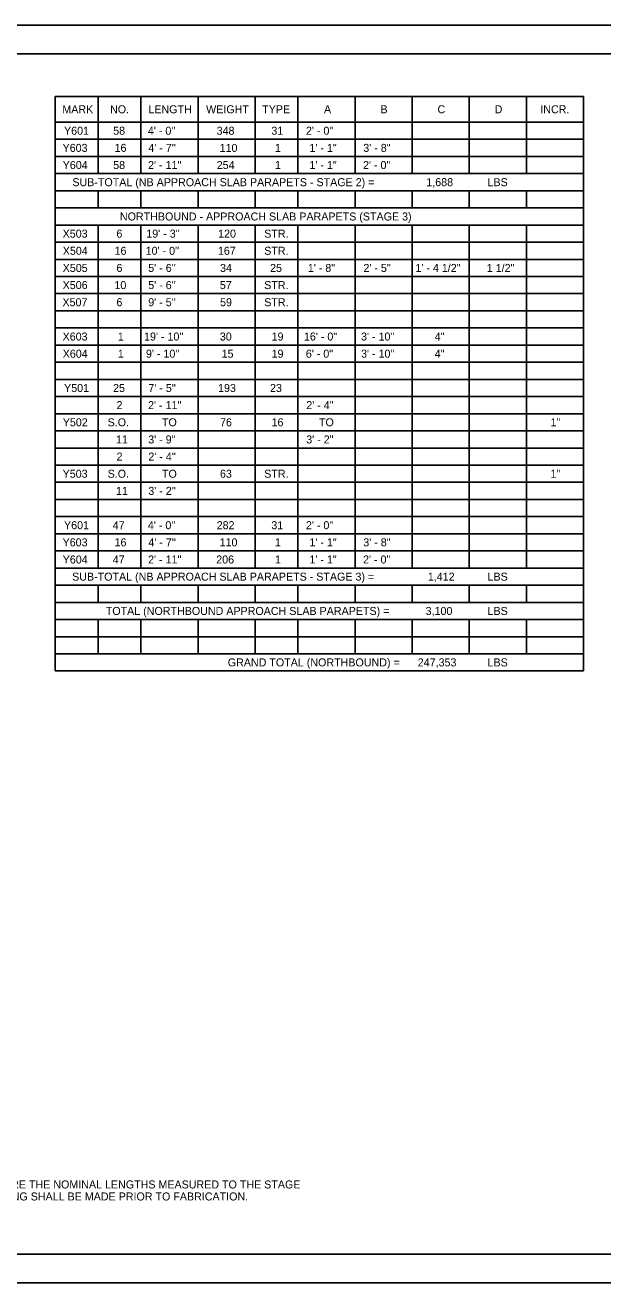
# Model space of a CAD drawing. Extents: x 1485751 to 1485785, y 230696.6 to 230718.6.
# Drawn here: x 1485763.13 to 1485773.25, y 230696.64 to 230718.64 of the extents above; entities that cross this region are included whole.
import ezdxf

# ---------------------------------------------------------------- set-up
doc = ezdxf.new("R2010")
doc.units = 0
for name, color, linetype in [('SH_Border', 7, 'Continuous'), ('SH_Cut_Line', 7, 'Continuous'), ('TX_P_Misc', 7, 'Continuous')]:
    doc.layers.add(name, color=color, linetype=linetype)

msp = doc.modelspace()

# ---------------------------------------------------------------- linework, layer by layer
at = {"layer": 'SH_Border'}
msp.add_lwpolyline([(1485753.033, 230718.141), (1485784.533, 230718.141), (1485784.533, 230697.141), (1485753.033, 230697.141)], close=True, dxfattribs=at)
at = {"layer": 'SH_Cut_Line'}
msp.add_lwpolyline([(1485751.033, 230718.641), (1485785.033, 230718.641), (1485785.033, 230696.641), (1485751.033, 230696.641)], close=True, dxfattribs=at)
at = {"layer": 'TX_P_Misc'}
for p, q in [((1485763.658, 230717.394), (1485772.908, 230717.394)), ((1485763.658, 230717.394), (1485763.658, 230707.344)), ((1485764.408, 230717.394), (1485764.408, 230716.044)), ((1485765.158, 230717.394), (1485765.158, 230716.044)), ((1485766.158, 230717.394), (1485766.158, 230716.044)), ((1485767.158, 230717.394), (1485767.158, 230716.044)), ((1485767.908, 230717.394), (1485767.908, 230716.044)), ((1485768.908, 230717.394), (1485768.908, 230716.044)), ((1485769.908, 230717.394), (1485769.908, 230716.044)), ((1485770.908, 230717.394), (1485770.908, 230716.044)), ((1485771.908, 230717.394), (1485771.908, 230716.044)), ((1485772.908, 230717.394), (1485772.908, 230707.344)), ((1485763.658, 230716.944), (1485772.908, 230716.944)), ((1485763.658, 230716.644), (1485772.908, 230716.644)), ((1485763.658, 230716.344), (1485772.908, 230716.344)), ((1485763.658, 230716.044), (1485772.908, 230716.044)), ((1485763.658, 230715.744), (1485772.908, 230715.744)), ((1485764.408, 230715.744), (1485764.408, 230715.444)), ((1485765.158, 230715.744), (1485765.158, 230715.444)), ((1485766.158, 230715.744), (1485766.158, 230715.444)), ((1485767.158, 230715.744), (1485767.158, 230715.444)), ((1485767.908, 230715.744), (1485767.908, 230715.444)), ((1485768.908, 230715.744), (1485768.908, 230715.444)), ((1485769.908, 230715.744), (1485769.908, 230715.444)), ((1485770.908, 230715.744), (1485770.908, 230715.444)), ((1485771.908, 230715.744), (1485771.908, 230715.444)), ((1485763.658, 230715.444), (1485772.908, 230715.444)), ((1485763.658, 230715.144), (1485772.908, 230715.144)), ((1485764.408, 230715.144), (1485764.408, 230709.144)), ((1485765.158, 230715.144), (1485765.158, 230709.144)), ((1485766.158, 230715.144), (1485766.158, 230709.144)), ((1485767.158, 230715.144), (1485767.158, 230709.144)), ((1485767.908, 230715.144), (1485767.908, 230709.144)), ((1485768.908, 230715.144), (1485768.908, 230709.144)), ((1485769.908, 230715.144), (1485769.908, 230709.144)), ((1485770.908, 230715.144), (1485770.908, 230709.144)), ((1485771.908, 230715.144), (1485771.908, 230709.144)), ((1485763.658, 230714.844), (1485772.908, 230714.844)), ((1485763.658, 230714.544), (1485772.908, 230714.544)), ((1485763.658, 230714.244), (1485772.908, 230714.244)), ((1485763.658, 230713.944), (1485772.908, 230713.944)), ((1485763.658, 230713.644), (1485772.908, 230713.644)), ((1485763.658, 230713.344), (1485772.908, 230713.344)), ((1485763.658, 230713.044), (1485772.908, 230713.044)), ((1485763.658, 230712.744), (1485772.908, 230712.744)), ((1485763.658, 230712.444), (1485772.908, 230712.444)), ((1485763.658, 230712.144), (1485772.908, 230712.144)), ((1485763.658, 230711.844), (1485772.908, 230711.844)), ((1485763.658, 230711.544), (1485772.908, 230711.544)), ((1485763.658, 230711.244), (1485772.908, 230711.244)), ((1485763.658, 230710.944), (1485772.908, 230710.944)), ((1485763.658, 230710.644), (1485772.908, 230710.644)), ((1485763.658, 230710.344), (1485772.908, 230710.344)), ((1485763.658, 230710.044), (1485772.908, 230710.044)), ((1485763.658, 230709.744), (1485772.908, 230709.744)), ((1485763.658, 230709.444), (1485772.908, 230709.444)), ((1485763.658, 230709.144), (1485772.908, 230709.144)), ((1485763.658, 230708.844), (1485772.908, 230708.844)), ((1485764.408, 230708.844), (1485764.408, 230708.544)), ((1485765.158, 230708.844), (1485765.158, 230708.544)), ((1485766.158, 230708.844), (1485766.158, 230708.544)), ((1485767.158, 230708.844), (1485767.158, 230708.544)), ((1485767.908, 230708.844), (1485767.908, 230708.544)), ((1485768.908, 230708.844), (1485768.908, 230708.544)), ((1485769.908, 230708.844), (1485769.908, 230708.544)), ((1485770.908, 230708.844), (1485770.908, 230708.544)), ((1485771.908, 230708.844), (1485771.908, 230708.544)), ((1485763.658, 230708.544), (1485772.908, 230708.544)), ((1485763.658, 230708.244), (1485772.908, 230708.244)), ((1485764.408, 230708.244), (1485764.408, 230707.644)), ((1485765.158, 230708.244), (1485765.158, 230707.644)), ((1485766.158, 230708.244), (1485766.158, 230707.644)), ((1485767.158, 230708.244), (1485767.158, 230707.644)), ((1485767.908, 230708.244), (1485767.908, 230707.644)), ((1485768.908, 230708.244), (1485768.908, 230707.644)), ((1485769.908, 230708.244), (1485769.908, 230707.644)), ((1485770.908, 230708.244), (1485770.908, 230707.644)), ((1485771.908, 230708.244), (1485771.908, 230707.644)), ((1485763.658, 230707.944), (1485772.908, 230707.944)), ((1485763.658, 230707.644), (1485772.908, 230707.644)), ((1485763.658, 230707.344), (1485772.908, 230707.344))]:
    msp.add_line(p, q, dxfattribs=at)

# ---------------------------------------------------------------- texts
for s, p in [('MARK', (1485763.782, 230717.099)), ('NO.', (1485764.618, 230717.099)), ('LENGTH', (1485765.288, 230717.099)), ('WEIGHT', (1485766.3, 230717.099)), ('TYPE', (1485767.282, 230717.099)), ('A', (1485768.364, 230717.099)), ('B', (1485769.353, 230717.099)), ('C', (1485770.352, 230717.099)), ('D', (1485771.353, 230717.099)), ('INCR.', (1485772.152, 230717.099)), ('Y601', (1485763.811, 230716.724)), ('58', (1485764.672, 230716.724)), ("4' - 0''", (1485765.28, 230716.724)), ('348', (1485766.484, 230716.724)), ('31', (1485767.442, 230716.724)), ('2\' - 0"', (1485768.048, 230716.724)), ('Y603', (1485763.786, 230716.424)), ('16', (1485764.696, 230716.424)), ("4' - 7''", (1485765.288, 230716.424)), ('110', (1485766.536, 230716.424)), ('1', (1485767.504, 230716.424)), ('1\' - 1"', (1485768.109, 230716.424)), ('3\' - 8"', (1485769.052, 230716.424)), ('Y604', (1485763.788, 230716.124)), ('58', (1485764.672, 230716.124)), ("2' - 11''", (1485765.283, 230716.124)), ('254', (1485766.486, 230716.124)), ('1', (1485767.504, 230716.124)), ('1\' - 1"', (1485768.109, 230716.124)), ('2\' - 0"', (1485769.048, 230716.124)), ('SUB-TOTAL (NB APPROACH SLAB PARAPETS - STAGE 2) =', (1485763.957, 230715.824)), ('1,688', (1485770.156, 230715.824)), ('LBS', (1485771.228, 230715.824)), ('NORTHBOUND - APPROACH SLAB PARAPETS (STAGE 3)', (1485764.79, 230715.224)), ('X503', (1485763.787, 230714.924)), ('6', (1485764.729, 230714.924)), ("19' - 3''", (1485765.252, 230714.924)), ('120', (1485766.51, 230714.924)), ('STR.', (1485767.317, 230714.924)), ('X504', (1485763.789, 230714.624)), ('16', (1485764.696, 230714.624)), ("10' - 0''", (1485765.241, 230714.624)), ('167', (1485766.506, 230714.624)), ('STR.', (1485767.317, 230714.624)), ('X505', (1485763.788, 230714.324)), ('6', (1485764.729, 230714.324)), ("5' - 6''", (1485765.286, 230714.324)), ('34', (1485766.544, 230714.324)), ('25', (1485767.42, 230714.324)), ('1\' - 8"', (1485768.081, 230714.324)), ('2\' - 5"', (1485769.055, 230714.324)), ('1\' - 4 1/2"', (1485769.965, 230714.324)), (' 1 1/2"', (1485771.163, 230714.324)), ('X506', (1485763.787, 230714.024)), ('10', (1485764.694, 230714.024)), ("5' - 6''", (1485765.286, 230714.024)), ('57', (1485766.54, 230714.024)), ('STR.', (1485767.317, 230714.024)), ('X507', (1485763.784, 230713.724)), ('6', (1485764.729, 230713.724)), ("9' - 5''", (1485765.286, 230713.724)), ('59', (1485766.544, 230713.724)), ('STR.', (1485767.317, 230713.724)), ('X603', (1485763.786, 230713.124)), ('1', (1485764.754, 230713.124)), ("19' - 10''", (1485765.213, 230713.124)), ('30', (1485766.54, 230713.124)), ('19', (1485767.447, 230713.124)), ('16\' - 0"', (1485768.013, 230713.124)), ('3\' - 10"', (1485769.013, 230713.124)), (' 4"', (1485770.251, 230713.124)), ('X604', (1485763.788, 230712.824)), ('1', (1485764.754, 230712.824)), ("9' - 10''", (1485765.246, 230712.824)), ('15', (1485766.571, 230712.824)), ('19', (1485767.447, 230712.824)), ('6\' - 0"', (1485768.046, 230712.824)), ('3\' - 10"', (1485769.013, 230712.824)), (' 4"', (1485770.251, 230712.824)), ('Y501', (1485763.812, 230712.224)), ('25', (1485764.67, 230712.224)), ("7' - 5''", (1485765.288, 230712.224)), ('193', (1485766.509, 230712.224)), ('23', (1485767.419, 230712.224)), ('2', (1485764.731, 230711.924)), ("2' - 11''", (1485765.283, 230711.924)), ('2\' - 4"', (1485768.054, 230711.924)), ('Y502', (1485763.789, 230711.624)), ('S.O.', (1485764.575, 230711.624)), ('TO', (1485765.526, 230711.624)), ('76', (1485766.544, 230711.624)), ('16', (1485767.446, 230711.624)), ('TO', (1485768.276, 230711.624)), (' 1"', (1485772.279, 230711.624)), ('11', (1485764.721, 230711.324)), ("3' - 9''", (1485765.285, 230711.324)), ('3\' - 2"', (1485768.053, 230711.324)), ('2', (1485764.731, 230711.024)), ("2' - 4''", (1485765.288, 230711.024)), ('Y503', (1485763.787, 230710.724)), ('S.O.', (1485764.575, 230710.724)), ('TO', (1485765.526, 230710.724)), ('63', (1485766.542, 230710.724)), ('STR.', (1485767.317, 230710.724)), (' 1"', (1485772.279, 230710.724)), ('11', (1485764.721, 230710.424)), ("3' - 2''", (1485765.287, 230710.424)), ('Y601', (1485763.811, 230709.824)), ('47', (1485764.665, 230709.824)), ("4' - 0''", (1485765.28, 230709.824)), ('282', (1485766.485, 230709.824)), ('31', (1485767.442, 230709.824)), ('2\' - 0"', (1485768.048, 230709.824)), ('Y603', (1485763.786, 230709.524)), ('16', (1485764.696, 230709.524)), ("4' - 7''", (1485765.288, 230709.524)), ('110', (1485766.536, 230709.524)), ('1', (1485767.504, 230709.524)), ('1\' - 1"', (1485768.109, 230709.524)), ('3\' - 8"', (1485769.052, 230709.524)), ('Y604', (1485763.788, 230709.224)), ('47', (1485764.665, 230709.224)), ("2' - 11''", (1485765.283, 230709.224)), ('206', (1485766.477, 230709.224)), ('1', (1485767.504, 230709.224)), ('1\' - 1"', (1485768.109, 230709.224)), ('2\' - 0"', (1485769.048, 230709.224)), ('SUB-TOTAL (NB APPROACH SLAB PARAPETS - STAGE 3) =', (1485763.953, 230708.924)), ('1,412', (1485770.183, 230708.924)), ('LBS', (1485771.228, 230708.924)), ('TOTAL (NORTHBOUND APPROACH SLAB PARAPETS) =', (1485764.542, 230708.324)), ('3,100', (1485770.144, 230708.324)), ('LBS', (1485771.228, 230708.324)), ('GRAND TOTAL (NORTHBOUND) =', (1485766.679, 230707.424)), ('247,353', (1485770.006, 230707.424)), ('LBS', (1485771.228, 230707.424)), ('* - INDICATES BARS REQUIRING MECHANICAL CONNECTORS.  THE LENGTHS SHOWN IN THE TABLE ARE THE NOMINAL LENGTHS MEASURED TO THE STAGE', (1485753.586, 230698.292)), ('    CONSTRUCTION JOINT.  ADJUSTMENT IN THE LENGTHS OF THE BARS DUE TO MECHANICAL SPLICING SHALL BE MADE PRIOR TO FABRICATION.', (1485753.586, 230698.082))]:
    msp.add_text(s, height=0.14, dxfattribs=at).set_placement(p)

doc.saveas('drawing.dxf')
